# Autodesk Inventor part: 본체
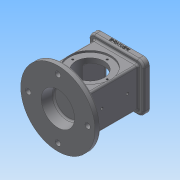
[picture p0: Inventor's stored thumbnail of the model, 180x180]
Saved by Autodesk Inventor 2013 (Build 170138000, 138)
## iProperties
Created: 2018-10
Part Number: 본체
Material: 일반
Document SubType Name: Modeling
Designer: Administrator
Density: 1 g/cm^3
Author: Administrator
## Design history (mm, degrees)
sketch "스케치1"
  geometry: C1 r 62.5 at (0, 0); 1 further point
  constraints: 1 centre point, 1 coincident
  dimensions: "d0" = 125 diameter of C1
extrude "돌출1" new body sketch "스케치1" distance "d1" = 10; taper "d2" = 0 deg
sketch "스케치2"
  geometry: L1 (-37, -33)-(37, -33); L2 (37, -33)-(37, 33); L3 (37, 33)-(-37, 33); L4 (-37, 33)-(-37, -33); L5 (-37, -33)-(37, 33); L6 (37, -33)-(-37, 33); C1 r 62.5 at (0, 0) reference
  constraints: 12 end point, 2 midpoint, 2 parallel, 1 horizontal, 1 perpendicular
  dimensions: "d3" = 74 distance of L3.end L2.end; "d4" = 66 distance of L2.end L1.end
extrude "돌출2" join sketch "스케치2" distance "d5" = 88; taper "d6" = 0 deg
sketch "스케치4"
  geometry: L1 (-46, -41)-(46, -41); L2 (46, -41)-(46, 41); L3 (46, 41)-(-46, 41); L4 (-46, 41)-(-46, -41); L5 (-46, -41)-(46, 41); L6 (46, -41)-(-46, 41); 1 further point
  constraints: 12 end point, 2 midpoint, 2 parallel, 1 horizontal, 1 perpendicular
  dimensions: "d7" = 92 distance of L3.end L2.end; "d8" = 82 distance of L2.end L1.end
extrude "돌출3" join sketch "스케치4" distance "d9" = 10; taper "d10" = 0 deg
sketch "스케치5"
  geometry: L1 (-26, -26)-(26, -26); L2 (26, -26)-(26, 26); L3 (26, 26)-(-26, 26); L4 (-26, 26)-(-26, -26); L5 (-26, -26)-(26, 26); L6 (26, -26)-(-26, 26); 1 further point
  constraints: 12 end point, 2 midpoint, 2 parallel, 1 horizontal, 1 perpendicular
  dimensions: "d11" = 52 distance of L3.end L2.end; "d12" = 52 distance between parallel lines of L1 L3
extrude "돌출4" cut sketch "스케치5" distance "d13" = 8; taper "d14" = 0 deg
sketch "스케치6"
  geometry: L1 (-22, -22)-(22, -22); L2 (22, -22)-(22, 22); L3 (22, 22)-(-22, 22); L4 (-22, 22)-(-22, -22); L5 (-22, -22)-(22, 22); L6 (22, -22)-(-22, 22); 1 further point
  constraints: 12 end point, 2 midpoint, 2 parallel, 1 horizontal, 1 perpendicular
  dimensions: "d15" = 44 distance of L3.end L2.end; "d16" = 44 distance of L2.end L1.end
extrude "돌출5" cut sketch "스케치6" distance "d17" = 82; taper "d18" = 0 deg
sketch "스케치9"
  geometry: L1 (-25.5, -10)-(99.5, -10) reference; C1 r 35 at (37, 44); 1 further point
  constraints: 1 centre point, 1 vertical alignment
  dimensions: "d19" = 70 diameter of C1; "d20" = 54 distance from line of L1 C1.centre
extrude "돌출6" cut sketch "스케치9" distance "d21" = 3; taper "d22" = 0 deg
fillet "모깎기1" dims "d23" = 3
fillet "모깎기2" dims "d24" = 3
fillet "모깎기3" dims "d25" = 10
fillet "모깎기4" dims "d26" = 3
sketch "스케치10"
  geometry: C1 r 35 at (0, 0) reference; C2 r 24 at (0, 0); 1 further point
  constraints: 1 centre point, 1 coincident
  dimensions: "d27" = 48 diameter of C2
extrude "돌출7" cut sketch "스케치10" distance "d28" = 93.25; taper "d29" = 0 deg
sketch "스케치11"
  geometry: C1 r 62.5 at (0, 0) reference; C2 r 28 at (0, 0)
  constraints: 1 centre point, 1 coincident
  dimensions: "d30" = 56 diameter of C2
extrude "돌출8" cut sketch "스케치11" distance "d31" = 18; taper "d32" = -10 deg
sketch "스케치12"
  geometry: L1 (-32.5, -13)-(92.5, -13) reference; 4 further points
  constraints: 2 vertical alignment, 1 midpoint
  dimensions: "d33" = 43 distance of point (30, 24) point (30, 67); "d35" = 37 distance from line of L1 point (30, 24)
hole "구멍1" sketch "스케치12" at (30, 67), (30, 24) diameter "d36" = 4.134; stored, may be unused: countersink angle "d40" = 90 deg, drill point angle "d42" = 118 deg; dims "d37" = 28, "d38" = 4, "d39" = 2, "d41" = 28
sketch "스케치13"
  geometry: C1 r 24 at (0, 0) reference; 2 further points
  constraints: 1 vertical alignment
  dimensions: "d43" = 29 distance of C1.centre point (0, 29)
hole "구멍2" sketch "스케치13" at (0, 29) diameter "d44" = 3.242; stored, may be unused: countersink angle "d48" = 90 deg, drill point angle "d50" = 118 deg; dims "d45" = 4, "d46" = 4, "d47" = 2, "d49" = 6
sketch "스케치14"
  geometry: A1 r 10 centre (-36, 31) between (-36, 41) and (-46, 31) reference; 2 further points
  constraints: 1 coincident
hole "구멍3" sketch "스케치14" at (-36, 31) diameter "d54" = 3.242; stored, may be unused: countersink angle "d58" = 90 deg, drill point angle "d60" = 118 deg; dims "d55" = 4, "d56" = 4, "d57" = 2, "d59" = 6
sketch "스케치15"
  geometry: C1 r 59.5 at (0, 0) reference; C2 r 4.5 at (0, 50)
  constraints: 1 centre point, 1 vertical alignment
  dimensions: "d67" = 9 diameter of C2; "d69" = 50 distance of C1.centre C2.centre
extrude "돌출9" cut sketch "스케치15" distance "d70" = 18; taper "d71" = 0 deg
fillet "모깎기5" dims "d75" = 3
chamfer "모따기1" distance "d76" = 1; stored, may be unused: second distance "d77" = 2, angle "d78" = 45 deg
sketch "스케치16"
  geometry: L1 (0, 0)-(72, 0) reference; L2 (-10, 0)-(-10, -7) reference; 2 further points
  constraints: 1 other
  dimensions: "d79" = 46 distance from line of L2 point (36, -4); "d80" = 4 distance from line of L1 point (36, -4)
feature "엠보싱1" sketch "스케치16" dims "d81" = 0.5, "d82" = 0
node "솔리드1"
mirror "대칭1"
pattern_circular "원형 패턴1" dims angle "d52" = 360 deg
mirror "대칭2"
pattern_linear "직사각형 패턴1" dims "d63" = 72, "d66" = 62
pattern_circular "원형 패턴2" dims angle "d73" = 360 deg
